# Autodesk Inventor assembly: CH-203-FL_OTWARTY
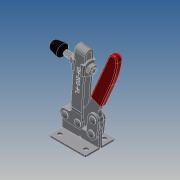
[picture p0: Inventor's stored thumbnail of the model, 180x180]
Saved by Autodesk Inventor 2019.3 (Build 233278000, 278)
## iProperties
Company: Î¢ÈíÖÐ¹ú
Created: 2012-09
Part Number: CH-203-FL_OTWARTY
Material: Ogólny
Description: STEP AP203
Document SubType Name: Assembly
Designer: CADENGINEERING4
Sending System: SolidWorks 2010
Preprocessor: SwSTEP 2.0
Title: CH-203-FL.STEP
Author: Î¢ÈíÓÃ»§
Revision Number: ÈÎºÎ
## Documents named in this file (9)
- E:\STRONA\Horizontal toggle clamp\CH-203-FL\CH-203-FL_OTWARTY.iam
- E:\STRONA\Horizontal toggle clamp\CH-203-FL\203-F-04.ipt
- E:\STRONA\Horizontal toggle clamp\CH-203-FL\225-D-06.ipt
- E:\STRONA\Horizontal toggle clamp\CH-203-FL\203-FL-02.ipt
- E:\STRONA\Horizontal toggle clamp\CH-203-FL\FW516.ipt
- E:\STRONA\Horizontal toggle clamp\CH-203-FL\203-F-01.ipt
- E:\STRONA\Horizontal toggle clamp\CH-203-FL\56212-02.ipt
- E:\STRONA\Horizontal toggle clamp\CH-203-FL\03.iam
- E:\STRONA\Horizontal toggle clamp\CH-203-FL\56212.ipt
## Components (14 placed, 14 different names)
1. 203-F-04_1 — Zestawiające:11, Zestawiające:13, Zestawiające:14
2. 203-F-04_2 — Zestawiające:10, Zestawiające:12, Zestawiające:13, Zestawiające:14, Zestawiające:15, Zestawiające:16, Zestawiające:17, Zestawiające:18, Zestawiające:20
3. 225-D-06_3 — Zestawiające:23, Zestawiające:24
4. 203-FL-02_4 — Równoległe:1, Zestawiające:6, Zestawiające:7, Zestawiające:9, Zestawiające:21, Zestawiające:22, Zestawiające:23, Zestawiające:24, Zestawiające:25, Zestawiające:26
5. FW516_5 — Równoległe:2, Zestawiające:2, Zestawiające:7, Zestawiające:8
6. 203-F-01_6 — Zestawiające:10, Zestawiające:11, Zestawiające:12, Zestawiające:21, Zestawiające:22, Przejściowe:1
7. 225-D-06_7 — Zestawiające:19, Zestawiające:20
8. 56212-02_8 — Zestawiające:1, Zestawiające:8
9. 56212-02_9 — Równoległe:3, Zestawiające:4, Zestawiające:5
10. 03_10 [sub-assembly] — Zestawiające:17, Zestawiające:18, Zestawiające:19, Zestawiające:27, Przejściowe:1
11. 225-D-06_11 — Zestawiające:25, Zestawiające:26, Zestawiające:27
12. FW516_12 — Równoległe:1, Równoległe:2, Zestawiające:3, Zestawiające:5, Zestawiające:6
13. 56212_13 — Równoległe:3, Zestawiające:1, Zestawiające:2, Zestawiające:3, Zestawiające:4, Zestawiające:9
14. 225-D-06_14 — Zestawiające:15, Zestawiające:16
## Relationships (31: Mate 27, Flush 3, Transitional 1)
- Równoległe:1 [Flush]: 203-FL-02_4 ↔ FW516_12
- Równoległe:2 [Flush]: FW516_5 ↔ FW516_12
- Równoległe:3 [Flush]: 56212-02_9 ↔ 56212_13
- Zestawiające:1 [Mate]: 56212-02_8 ↔ 56212_13
- Zestawiające:2 [Mate]: FW516_5 ↔ 56212_13
- Zestawiające:3 [Mate]: FW516_12 ↔ 56212_13
- Zestawiające:4 [Mate]: 56212-02_9 ↔ 56212_13
- Zestawiające:5 [Mate]: 56212-02_9 ↔ FW516_12
- Zestawiające:6 [Mate]: 203-FL-02_4 ↔ FW516_12
- Zestawiające:7 [Mate]: 203-FL-02_4 ↔ FW516_5
- Zestawiające:8 [Mate]: FW516_5 ↔ 56212-02_8
- Zestawiające:9 [Mate]: 203-FL-02_4 ↔ 56212_13
- Zestawiające:10 [Mate]: 203-F-04_2 ↔ 203-F-01_6
- Zestawiające:11 [Mate]: 203-F-04_1 ↔ 203-F-01_6
- Zestawiające:12 [Mate]: 203-F-04_2 ↔ 203-F-01_6
- Zestawiające:13 [Mate]: 203-F-04_1 ↔ 203-F-04_2
- Zestawiające:14 [Mate]: 203-F-04_1 ↔ 203-F-04_2
- Zestawiające:15 [Mate]: 203-F-04_2 ↔ 225-D-06_14
- Zestawiające:16 [Mate]: 203-F-04_2 ↔ 225-D-06_14
- Zestawiające:17 [Mate]: 203-F-04_2 ↔ 03_10
- Zestawiające:18 [Mate]: 203-F-04_2 ↔ 03_10
- Zestawiające:19 [Mate]: 225-D-06_7 ↔ 03_10
- Zestawiające:20 [Mate]: 203-F-04_2 ↔ 225-D-06_7
- Zestawiające:21 [Mate]: 203-FL-02_4 ↔ 203-F-01_6
- Zestawiające:22 [Mate]: 203-FL-02_4 ↔ 203-F-01_6
- Zestawiające:23 [Mate]: 225-D-06_3 ↔ 203-FL-02_4
- Zestawiające:24 [Mate]: 225-D-06_3 ↔ 203-FL-02_4
- Zestawiające:25 [Mate]: 203-FL-02_4 ↔ 225-D-06_11
- Zestawiające:26 [Mate]: 203-FL-02_4 ↔ 225-D-06_11
- Zestawiające:27 [Mate]: 03_10 ↔ 225-D-06_11
- Przejściowe:1 [Transitional]: 203-F-01_6 ↔ 03_10
